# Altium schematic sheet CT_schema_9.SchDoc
size 278 x 170 mm
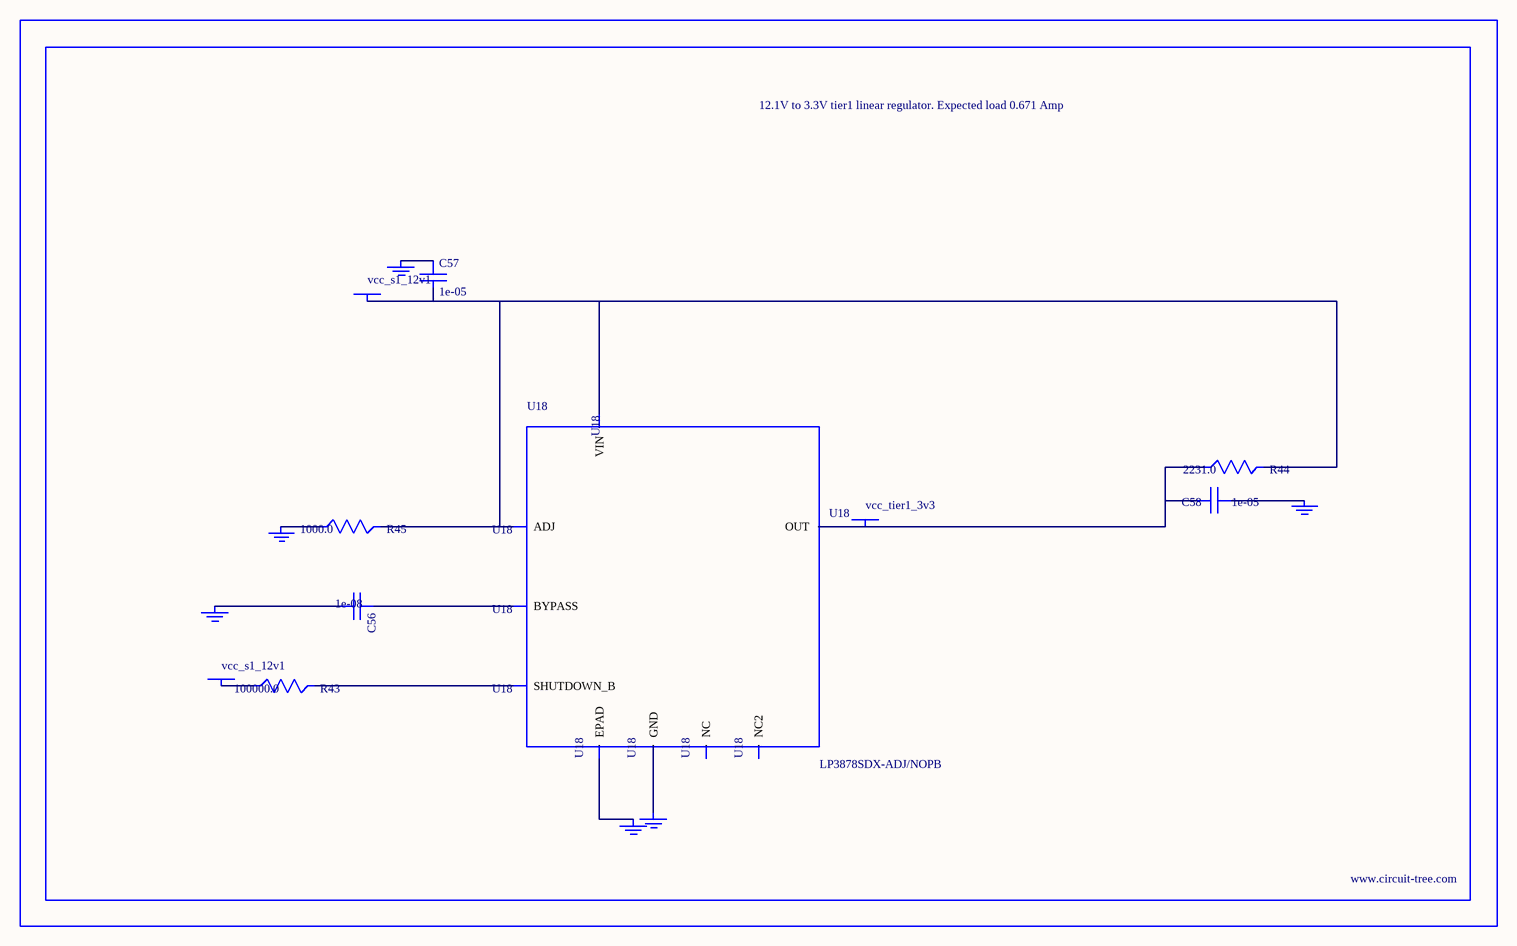
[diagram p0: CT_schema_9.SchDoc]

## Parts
BORDER8  (no value)
C56  1e-08  [C0402]
C57  1e-05  [C1210]
C58  1e-05  [C1210]
GND_INSTANCE_8_0  (no value)
GND_INSTANCE_8_1  (no value)
GND_INSTANCE_8_2  (no value)
GND_INSTANCE_8_3  (no value)
GND_INSTANCE_8_4  (no value)
GND_INSTANCE_8_5  (no value)
POWER_INSTANCE_8_0  vcc_s1_12v1
POWER_INSTANCE_8_1  vcc_s1_12v1
POWER_INSTANCE_8_2  vcc_tier1_3v3
R43  100000.0  [R0603]
R44  2231.0  [R0603]
R45  1000.0  [R0603]
U18  LP3878SDX-ADJ/NOPB  [WSON-8]

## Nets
NetC56_1: C56.1 U18.1(BYPASS)
NetC56_2: C56.2 GND_INSTANCE_8_0.0(GND)
NetC57_1: C57.1 GND_INSTANCE_8_1.0(GND)
NetC57_2: C57.2 POWER_INSTANCE_8_0.0(PWR) R44.2 R45.2 U18.4(VIN) U18.6(ADJ)
NetC58_1: C58.1 GND_INSTANCE_8_2.0(GND)
NetC58_2: C58.2 POWER_INSTANCE_8_2.0(PWR) R44.1 U18.5(OUT)
NetGND_INSTANCE_8_3_0: GND_INSTANCE_8_3.0(GND) R45.1
NetGND_INSTANCE_8_4_0: GND_INSTANCE_8_4.0(GND) U18.PAD(EPAD)
NetGND_INSTANCE_8_5_0: GND_INSTANCE_8_5.0(GND) U18.3(GND)
NetPOWER_INSTANCE_8_1_0: POWER_INSTANCE_8_1.0(PWR) R43.1
NetR43_2: R43.2 U18.8(SHUTDOWN_B)

Not connected (* = marked no-connect by the designer): U18 2(NC) 7(NC2)

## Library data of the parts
BORDER8 = BORDER_PAGE8
C56 = C0402C103K3RAC
C57 = C1210C106K5PACTU
C58 = GRM32DR61E106MA12L
GND_INSTANCE_8_0-GND_INSTANCE_8_5 = GND
POWER_INSTANCE_8_0-POWER_INSTANCE_8_2 = PWR
R43 = RC0603JR-07100KL
R44 = R44
R45 = RC0603JR-071KL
